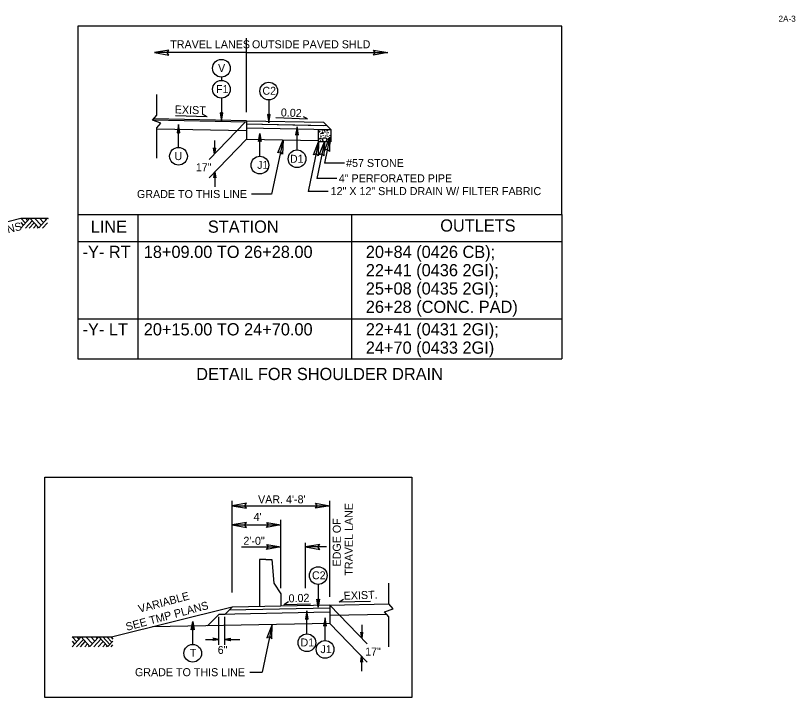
# Model space of a CAD drawing. Extents: x 1901582 to 1902252, y 193723 to 194156.
# Drawn here: x 1902064.9 to 1902128.8, y 193879.3 to 193935.2 of the extents above; entities that cross this region are included whole.
import ezdxf

# ---------------------------------------------------------------- set-up
doc = ezdxf.new("R2010")
doc.units = 0
for name, color, linetype in [('Old_Level_1', 7, 'Continuous'), ('Old_Level_11', 7, 'Continuous'), ('Old_Level_2', 7, 'Continuous'), ('Old_Level_20', 7, 'Continuous'), ('Old_Level_44', 7, 'Continuous'), ('Prop Dimension', 7, 'Continuous'), ('Typical Curb CELL', 7, 'Continuous'), ('Typical Median Barrier CELL', 7, 'Continuous'), ('Typical Pavement Slope Information CELL', 7, 'Continuous'), ('Typical Terminator CELL', 7, 'Continuous'), ('Typical Text Asphalt at Bridge Approach CELL', 7, 'Continuous')]:
    doc.layers.add(name, color=color, linetype=linetype)

msp = doc.modelspace()

# ---------------------------------------------------------------- linework, layer by layer
at = {"layer": 'Old_Level_1'}
for p, q in [((1902083.794, 193927.288), (1902083.794, 193933.361)), ((1902083.794, 193932.177), (1902076.259, 193932.177)), ((1902083.794, 193932.177), (1902095.364, 193932.177)), ((1902083.794, 193926.463), (1902076.121, 193926.617)), ((1902083.794, 193926.577), (1902076.174, 193926.73)), ((1902083.794, 193926.577), (1902090.11, 193926.451)), ((1902083.794, 193926.577), (1902083.794, 193925.077)), ((1902086.201, 193926.841), (1902088.787, 193926.739)), ((1902088.787, 193926.739), (1902088.457, 193926.912)), ((1902083.709, 193926.49), (1902080.725, 193923.408)), ((1902083.794, 193926.327), (1902090.365, 193926.196)), ((1902083.794, 193926.327), (1902090.104, 193926.201)), ((1902083.794, 193925.994), (1902090.705, 193925.856)), ((1902090.11, 193926.451), (1902090.705, 193925.856)), ((1902083.794, 193925.744), (1902076.442, 193925.891)), ((1902083.794, 193925.077), (1902080.725, 193921.908)), ((1902081.174, 193924.96), (1902081.174, 193923.872)), ((1902083.794, 193925.077), (1902089.705, 193924.959)), ((1902086.785, 193925.017), (1902085.851, 193920.553)), ((1902089.705, 193924.856), (1902088.855, 193920.794)), ((1902090.178, 193924.856), (1902089.548, 193921.842)), ((1902090.621, 193925.229), (1902090.175, 193923.098)), ((1902081.174, 193923.872), (1902081.09, 193924.349)), ((1902081.174, 193923.872), (1902081.102, 193924.34)), ((1902081.114, 193924.331), (1902081.174, 193923.872)), ((1902081.174, 193923.872), (1902081.126, 193924.323)), ((1902081.138, 193924.314), (1902081.174, 193923.872)), ((1902081.174, 193923.872), (1902081.15, 193924.305)), ((1902081.162, 193924.296), (1902081.174, 193923.872)), ((1902081.174, 193923.872), (1902081.259, 193924.349)), ((1902081.247, 193924.34), (1902081.174, 193923.872)), ((1902081.174, 193923.872), (1902081.234, 193924.331)), ((1902081.222, 193924.323), (1902081.174, 193923.872)), ((1902081.174, 193923.872), (1902081.21, 193924.314)), ((1902081.198, 193924.305), (1902081.174, 193923.872)), ((1902081.174, 193923.872), (1902081.186, 193924.296)), ((1902081.174, 193924.287), (1902081.174, 193923.872)), ((1902091.811, 193923.098), (1902090.175, 193923.098)), ((1902081.191, 193922.389), (1902081.107, 193921.911)), ((1902081.119, 193921.921), (1902081.191, 193922.389)), ((1902081.191, 193922.389), (1902081.131, 193921.929)), ((1902081.143, 193921.939), (1902081.191, 193922.389)), ((1902081.191, 193922.389), (1902081.155, 193921.947)), ((1902081.167, 193921.955), (1902081.191, 193922.389)), ((1902081.191, 193922.389), (1902081.179, 193921.964)), ((1902081.191, 193922.389), (1902081.276, 193921.911)), ((1902081.203, 193921.964), (1902081.191, 193922.389)), ((1902081.191, 193922.389), (1902081.215, 193921.955)), ((1902081.227, 193921.947), (1902081.191, 193922.389)), ((1902081.191, 193922.389), (1902081.239, 193921.939)), ((1902081.251, 193921.929), (1902081.191, 193922.389)), ((1902081.191, 193922.389), (1902081.264, 193921.921)), ((1902081.191, 193922.389), (1902081.191, 193921.163)), ((1902091.183, 193921.842), (1902089.548, 193921.842)), ((1902085.851, 193920.553), (1902084.216, 193920.553)), ((1902090.491, 193920.794), (1902088.855, 193920.794)), ((1902058.003, 193916.768), (1902065.307, 193918.594)), ((1902082.619, 193887.917), (1902082.619, 193895.416)), ((1902082.619, 193895.027), (1902090.619, 193895.027)), ((1902082.619, 193893.454), (1902086.619, 193893.454)), ((1902086.619, 193888.281), (1902086.619, 193893.86)), ((1902088.619, 193888.281), (1902088.619, 193891.983)), ((1902090.349, 193891.645), (1902088.619, 193891.645)), ((1902090.619, 193886.879), (1902095.451, 193886.975)), ((1902082.619, 193886.719), (1902072.852, 193884.277)), ((1902082.619, 193886.719), (1902082.024, 193886.123)), ((1902090.619, 193886.628), (1902082.364, 193886.463)), ((1902090.619, 193886.879), (1902082.619, 193886.719)), ((1902090.619, 193886.879), (1902090.619, 193885.378)), ((1902090.619, 193886.879), (1902093.688, 193883.709)), ((1902081.524, 193886.113), (1902080.589, 193885.178)), ((1902090.619, 193886.295), (1902081.524, 193886.113)), ((1902082.024, 193886.123), (1902081.524, 193886.113)), ((1902090.619, 193886.045), (1902095.271, 193886.138)), ((1902090.619, 193885.378), (1902076.097, 193885.088)), ((1902085.905, 193885.284), (1902085.088, 193881.375)), ((1902090.619, 193885.378), (1902093.688, 193882.209)), ((1902093.239, 193885.261), (1902093.239, 193884.173)), ((1902093.239, 193884.173), (1902093.154, 193884.65)), ((1902093.166, 193884.641), (1902093.239, 193884.173)), ((1902093.239, 193884.173), (1902093.179, 193884.632)), ((1902093.191, 193884.624), (1902093.239, 193884.173)), ((1902093.239, 193884.173), (1902093.203, 193884.615)), ((1902093.215, 193884.606), (1902093.239, 193884.173)), ((1902093.239, 193884.173), (1902093.227, 193884.597)), ((1902093.239, 193884.173), (1902093.323, 193884.65)), ((1902093.239, 193884.173), (1902093.311, 193884.641)), ((1902093.299, 193884.632), (1902093.239, 193884.173)), ((1902093.239, 193884.173), (1902093.287, 193884.624)), ((1902093.275, 193884.615), (1902093.239, 193884.173)), ((1902093.239, 193884.173), (1902093.263, 193884.606)), ((1902093.251, 193884.597), (1902093.239, 193884.173)), ((1902093.239, 193884.588), (1902093.239, 193884.173)), ((1902080.436, 193884.075), (1902081.524, 193884.075)), ((1902081.524, 193884.075), (1902081.047, 193884.159)), ((1902081.524, 193884.075), (1902081.047, 193883.99)), ((1902081.524, 193884.075), (1902081.056, 193884.147)), ((1902081.056, 193884.002), (1902081.524, 193884.075)), ((1902081.065, 193884.135), (1902081.524, 193884.075)), ((1902081.524, 193884.075), (1902081.065, 193884.015)), ((1902081.524, 193884.075), (1902081.073, 193884.123)), ((1902081.073, 193884.027), (1902081.524, 193884.075)), ((1902081.082, 193884.111), (1902081.524, 193884.075)), ((1902081.524, 193884.075), (1902081.082, 193884.039)), ((1902081.524, 193884.075), (1902081.091, 193884.099)), ((1902081.091, 193884.051), (1902081.524, 193884.075)), ((1902081.1, 193884.087), (1902081.524, 193884.075)), ((1902081.524, 193884.075), (1902081.1, 193884.063)), ((1902081.109, 193884.075), (1902081.524, 193884.075)), ((1902082.024, 193884.058), (1902082.502, 193884.142)), ((1902082.492, 193884.131), (1902082.024, 193884.058)), ((1902082.024, 193884.058), (1902082.484, 193884.119)), ((1902082.474, 193884.107), (1902082.024, 193884.058)), ((1902082.024, 193884.058), (1902082.466, 193884.094)), ((1902082.458, 193884.082), (1902082.024, 193884.058)), ((1902082.024, 193884.058), (1902082.449, 193884.07)), ((1902082.024, 193884.058), (1902082.502, 193883.974)), ((1902082.449, 193884.046), (1902082.024, 193884.058)), ((1902082.024, 193884.058), (1902082.458, 193884.034)), ((1902082.466, 193884.023), (1902082.024, 193884.058)), ((1902082.024, 193884.058), (1902082.474, 193884.011)), ((1902082.484, 193883.999), (1902082.024, 193884.058)), ((1902082.024, 193884.058), (1902082.492, 193883.985)), ((1902082.024, 193884.058), (1902083.25, 193884.058)), ((1902093.222, 193882.69), (1902093.138, 193882.212)), ((1902093.222, 193882.69), (1902093.149, 193882.222)), ((1902093.163, 193882.23), (1902093.222, 193882.69)), ((1902093.222, 193882.69), (1902093.175, 193882.24)), ((1902093.187, 193882.248), (1902093.222, 193882.69)), ((1902093.222, 193882.69), (1902093.198, 193882.256)), ((1902093.21, 193882.265), (1902093.222, 193882.69)), ((1902093.222, 193882.69), (1902093.306, 193882.212)), ((1902093.295, 193882.222), (1902093.222, 193882.69)), ((1902093.222, 193882.69), (1902093.283, 193882.23)), ((1902093.271, 193882.24), (1902093.222, 193882.69)), ((1902093.222, 193882.69), (1902093.258, 193882.248)), ((1902093.246, 193882.256), (1902093.222, 193882.69)), ((1902093.222, 193882.69), (1902093.234, 193882.265)), ((1902093.222, 193882.69), (1902093.222, 193881.464)), ((1902084.078, 193881.375), (1902085.088, 193881.375))]:
    msp.add_line(p, q, dxfattribs=at)
for points in [[(1902065.307, 193918.594), (1902067.543, 193918.594)], [(1902069.51, 193884.277), (1902072.852, 193884.277)]]:
    msp.add_lwpolyline(points, dxfattribs=at)
msp.add_lwpolyline([(1902097.341, 193879.316), (1902067.284, 193879.316), (1902067.284, 193897.368), (1902097.341, 193897.368)], close=True, dxfattribs=at)
at = {"layer": 'Old_Level_11'}
for p, q in [((1902081.741, 193930.16), (1902081.741, 193929.882)), ((1902081.741, 193928.432), (1902081.741, 193926.558)), ((1902085.618, 193928.288), (1902085.618, 193926.414)), ((1902078.225, 193924.396), (1902078.225, 193926.271)), ((1902087.932, 193924.188), (1902087.932, 193926.091)), ((1902084.89, 193923.669), (1902084.89, 193925.543)), ((1902069.979, 193918.885), (1902069.979, 193907.075)), ((1902074.892, 193918.885), (1902074.892, 193907.075)), ((1902092.407, 193918.885), (1902092.407, 193907.075)), ((1902109.632, 193918.885), (1902109.632, 193907.075)), ((1902065.307, 193918.594), (1902065.682, 193918.191)), ((1902065.307, 193917.789), (1902066.049, 193918.586)), ((1902065.681, 193917.789), (1902066.235, 193918.385)), ((1902065.682, 193918.594), (1902065.869, 193918.393)), ((1902066.049, 193918.586), (1902066.773, 193917.807)), ((1902066.44, 193918.594), (1902066.973, 193918.021)), ((1902066.773, 193917.807), (1902067.504, 193918.593)), ((1902066.838, 193918.594), (1902067.171, 193918.235)), ((1902067.24, 193918.594), (1902067.373, 193918.451)), ((1902067.504, 193918.593), (1902067.539, 193918.556)), ((1902065.307, 193918.232), (1902065.513, 193918.01)), ((1902065.99, 193917.789), (1902066.391, 193918.218)), ((1902066.337, 193917.789), (1902066.564, 193918.032)), ((1902066.648, 193917.789), (1902066.719, 193917.865)), ((1902067.083, 193917.789), (1902067.49, 193918.226)), ((1902069.979, 193916.681), (1902109.632, 193916.681)), ((1902069.979, 193910.332), (1902109.632, 193910.332)), ((1902069.979, 193907.075), (1902109.632, 193907.075)), ((1902089.668, 193888.58), (1902089.668, 193886.706)), ((1902088.743, 193884.526), (1902088.743, 193886.4)), ((1902090.234, 193883.976), (1902090.234, 193885.85)), ((1902079.387, 193883.66), (1902079.387, 193885.534)), ((1902069.51, 193884.277), (1902069.885, 193883.874)), ((1902069.51, 193883.472), (1902070.252, 193884.269)), ((1902069.51, 193883.915), (1902069.716, 193883.693)), ((1902069.884, 193883.472), (1902070.438, 193884.068)), ((1902069.885, 193884.277), (1902070.072, 193884.076)), ((1902070.193, 193883.472), (1902070.594, 193883.901)), ((1902070.252, 193884.269), (1902070.976, 193883.49)), ((1902070.643, 193884.277), (1902071.176, 193883.704)), ((1902070.976, 193883.49), (1902071.707, 193884.276)), ((1902071.041, 193884.277), (1902071.374, 193883.918)), ((1902071.286, 193883.472), (1902071.872, 193884.1)), ((1902071.443, 193884.277), (1902071.576, 193884.134)), ((1902071.656, 193883.472), (1902072.056, 193883.901)), ((1902071.707, 193884.276), (1902072.448, 193883.48)), ((1902072.029, 193884.277), (1902072.609, 193883.654)), ((1902072.362, 193884.277), (1902072.776, 193883.833)), ((1902072.448, 193883.48), (1902072.852, 193883.915)), ((1902072.682, 193884.277), (1902072.852, 193884.094)), ((1902070.54, 193883.472), (1902070.767, 193883.715)), ((1902070.851, 193883.472), (1902070.922, 193883.548)), ((1902072.022, 193883.472), (1902072.239, 193883.705)), ((1902072.317, 193883.472), (1902072.386, 193883.546)), ((1902072.718, 193883.472), (1902072.852, 193883.615))]:
    msp.add_line(p, q, dxfattribs=at)
for points in [[(1902109.632, 193934.341), (1902069.979, 193934.341), (1902069.979, 193918.885), (1902109.632, 193918.885)], [(1902081.625, 193927.229), (1902081.741, 193926.558), (1902081.86, 193927.233), (1902081.741, 193927.147)], [(1902085.502, 193927.085), (1902085.618, 193926.414), (1902085.737, 193927.089), (1902085.618, 193927.003)], [(1902078.341, 193925.599), (1902078.225, 193926.271), (1902078.106, 193925.595), (1902078.225, 193925.681)], [(1902088.048, 193925.419), (1902087.932, 193926.091), (1902087.813, 193925.416), (1902087.932, 193925.501)], [(1902084.775, 193924.871), (1902084.89, 193925.543), (1902085.01, 193924.868), (1902084.89, 193924.953)], [(1902089.784, 193887.377), (1902089.668, 193886.706), (1902089.549, 193887.381), (1902089.668, 193887.295)], [(1902088.858, 193885.729), (1902088.743, 193886.4), (1902088.623, 193885.725), (1902088.743, 193885.811)], [(1902090.349, 193885.179), (1902090.234, 193885.85), (1902090.114, 193885.175), (1902090.234, 193885.261)], [(1902079.272, 193884.863), (1902079.387, 193885.534), (1902079.507, 193884.859), (1902079.387, 193884.945)]]:
    msp.add_lwpolyline(points, close=True, dxfattribs=at)
for centre in [(1902081.741, 193930.885), (1902081.741, 193929.157), (1902085.618, 193929.013), (1902078.225, 193923.671), (1902087.932, 193923.463), (1902084.89, 193922.944), (1902089.668, 193889.305), (1902088.743, 193883.801), (1902090.233, 193883.251), (1902079.387, 193882.935)]:
    msp.add_circle(centre, 0.725, dxfattribs=at)
at = {"layer": 'Prop Dimension'}
for p, q in [((1902090.619, 193887.571), (1902090.619, 193895.416)), ((1902083.396, 193891.645), (1902086.619, 193891.645)), ((1902081.524, 193883.621), (1902081.524, 193885.914)), ((1902082.024, 193883.621), (1902082.024, 193885.914))]:
    msp.add_line(p, q, dxfattribs=at)
at = {"layer": 'Typical Curb CELL'}
for p, q in [((1902089.705, 193924.856), (1902089.705, 193925.856)), ((1902089.705, 193925.856), (1902090.705, 193925.856)), ((1902089.963, 193925.527), (1902090.052, 193925.645)), ((1902090.084, 193925.531), (1902089.963, 193925.527)), ((1902090.052, 193925.645), (1902090.084, 193925.531)), ((1902090.705, 193925.856), (1902090.705, 193924.856)), ((1902090.705, 193924.856), (1902089.705, 193924.856)), ((1902089.774, 193925.071), (1902089.838, 193925.185)), ((1902089.94, 193925.108), (1902089.774, 193925.071)), ((1902089.838, 193925.185), (1902089.94, 193925.108)), ((1902090.468, 193925.048), (1902090.532, 193925.162)), ((1902090.634, 193925.085), (1902090.468, 193925.048)), ((1902090.532, 193925.162), (1902090.634, 193925.085))]:
    msp.add_line(p, q, dxfattribs=at)
for centre, radius in [((1902089.709, 193925.321), 0.00802), ((1902089.721, 193925.629), 0.00802), ((1902089.74, 193925.726), 0.00802), ((1902089.775, 193925.485), 0.00802), ((1902089.796, 193925.69), 0.00802), ((1902089.841, 193925.316), 0.00802), ((1902089.872, 193925.529), 0.00802), ((1902089.907, 193925.813), 0.00802), ((1902089.919, 193925.294), 0.00802), ((1902090.002, 193925.726), 0.00802), ((1902090.05, 193925.827), 0.00802), ((1902090.08, 193925.359), 0.00802), ((1902090.197, 193925.761), 0.00802), ((1902090.223, 193925.659), 0.00802), ((1902090.285, 193925.332), 0.00802), ((1902090.37, 193925.57), 0.00802), ((1902090.401, 193925.416), 0.00802), ((1902090.402, 193925.741), 0.00802), ((1902090.42, 193925.791), 0.00802), ((1902090.456, 193925.3), 0.00802), ((1902090.496, 193925.596), 0.00802), ((1902090.535, 193925.293), 0.00802), ((1902090.634, 193925.36), 0.00802), ((1902090.676, 193925.758), 0.00802), ((1902089.85, 193924.927), 0.00802), ((1902090.205, 193925.022), 0.167), ((1902090.545, 193924.904), 0.00802)]:
    msp.add_circle(centre, radius, dxfattribs=at)
at = {"layer": 'Typical Median Barrier CELL'}
for p, q in [((1902085.37, 193890.631), (1902084.87, 193890.631)), ((1902084.87, 193890.631), (1902084.87, 193886.773)), ((1902085.37, 193890.631), (1902085.87, 193890.631)), ((1902085.87, 193890.631), (1902086.036, 193888.684)), ((1902086.036, 193888.684), (1902086.619, 193887.798)), ((1902086.619, 193887.798), (1902086.619, 193886.799))]:
    msp.add_line(p, q, dxfattribs=at)
at = {"layer": 'Typical Pavement Slope Information CELL'}
for p, q in [((1902080.565, 193926.889), (1902077.978, 193926.99)), ((1902080.565, 193926.889), (1902080.194, 193927.123)), ((1902086.861, 193886.936), (1902087.236, 193887.164)), ((1902086.861, 193886.936), (1902089.045, 193886.988)), ((1902091.374, 193887.15), (1902091.749, 193887.378)), ((1902091.374, 193887.15), (1902093.962, 193887.211))]:
    msp.add_line(p, q, dxfattribs=at)
at = {"layer": 'Typical Terminator CELL'}
for points in [[(1902077.431, 193932.379), (1902076.259, 193932.177), (1902077.437, 193931.969), (1902077.287, 193932.177)], [(1902094.192, 193932.379), (1902095.364, 193932.177), (1902094.185, 193931.969), (1902094.335, 193932.177)], [(1902086.36, 193923.942), (1902086.785, 193925.017), (1902086.749, 193923.854), (1902086.58, 193924.038)], [(1902089.279, 193923.78), (1902089.705, 193924.856), (1902089.669, 193923.692), (1902089.5, 193923.877)], [(1902089.753, 193923.78), (1902090.178, 193924.856), (1902090.142, 193923.692), (1902089.973, 193923.877)], [(1902090.195, 193924.153), (1902090.621, 193925.229), (1902090.585, 193924.065), (1902090.416, 193924.249)], [(1902083.791, 193895.228), (1902082.619, 193895.027), (1902083.798, 193894.818), (1902083.648, 193895.027)], [(1902089.448, 193895.228), (1902090.619, 193895.027), (1902089.441, 193894.818), (1902089.591, 193895.027)], [(1902083.791, 193893.656), (1902082.619, 193893.454), (1902083.798, 193893.246), (1902083.648, 193893.454)], [(1902085.448, 193893.656), (1902086.619, 193893.454), (1902085.441, 193893.246), (1902085.591, 193893.454)], [(1902085.448, 193891.847), (1902086.619, 193891.645), (1902085.441, 193891.437), (1902085.591, 193891.645)], [(1902089.791, 193891.847), (1902088.619, 193891.645), (1902089.798, 193891.437), (1902089.648, 193891.645)], [(1902085.864, 193884.128), (1902085.905, 193885.284), (1902085.472, 193884.204), (1902085.7, 193884.305)]]:
    msp.add_lwpolyline(points, close=True, dxfattribs=at)
at = {"layer": 'Typical Text Asphalt at Bridge Approach CELL'}
for points in [[(1902076.442, 193923.515), (1902076.442, 193925.99), (1902076.783, 193926.386), (1902076.087, 193926.629), (1902076.442, 193927.042), (1902076.445, 193928.744)], [(1902095.451, 193883.454), (1902095.451, 193885.929), (1902095.109, 193886.326), (1902095.805, 193886.568), (1902095.451, 193886.981), (1902095.447, 193888.683)]]:
    msp.add_lwpolyline(points, dxfattribs=at)

# ---------------------------------------------------------------- texts
at = {"layer": 'Old_Level_1'}
for s, p in [('TRAVEL LANES', (1902077.549, 193932.52)), ('OUTSIDE PAVED SHLD', (1902084.241, 193932.52)), ('#57 STONE', (1902091.953, 193922.79)), ('4" PERFORATED PIPE', (1902091.358, 193921.534)), ('GRADE TO THIS LINE', (1902074.823, 193920.246)), ('12" X 12" SHLD DRAIN W/ FILTER FABRIC', (1902090.689, 193920.486)), ("VAR. 4'-8'", (1902084.741, 193895.222)), ("4'", (1902084.375, 193893.788)), ('2\'-0"', (1902083.541, 193891.823)), ('GRADE TO THIS LINE', (1902074.658, 193881.055))]:
    msp.add_text(s, height=0.656, dxfattribs=at).set_placement(p)
for s, rotation, p in [('SEE X-SECTIONS', 14.03624, (1902058.302, 193915.861)), ('TRAVEL LANE', 90, (1902092.503, 193889.297)), ('EDGE OF', 90, (1902091.519, 193890.049)), ('VARIABLE', 15.042, (1902075.028, 193886.24)), ('SEE TMP PLANS', 15.042, (1902074.002, 193884.767))]:
    msp.add_text(s, height=0.656, rotation=rotation, dxfattribs=at).set_placement(p)
at = {"layer": 'Old_Level_11'}
for s, p in [('LINE', (1902071.036, 193917.402)), ('STATION', (1902080.63, 193917.402)), ('OUTLETS', (1902099.666, 193917.496)), ('-Y- RT ', (1902070.366, 193915.333)), ('18+09.00 TO 26+28.00', (1902075.38, 193915.333)), ('20+84 (0426 CB); ', (1902093.569, 193915.333)), ('22+41 (0436 2GI); ', (1902093.569, 193913.833)), ('25+08 (0435 2GI); ', (1902093.569, 193912.333)), ('26+28 (CONC. PAD)', (1902093.569, 193910.833)), ('-Y- LT ', (1902070.366, 193908.987)), ('20+15.00 TO 24+70.00', (1902075.38, 193908.987)), ('22+41 (0431 2GI); ', (1902093.569, 193908.987)), ('24+70 (0433 2GI)', (1902093.569, 193907.487)), ('DETAIL FOR SHOULDER DRAIN ', (1902079.675, 193905.327))]:
    msp.add_text(s, height=1, dxfattribs=at).set_placement(p)
at = {"layer": 'Old_Level_2'}
for s, rotation, p in [('EXIST', 358.02792, (1902077.913, 193927.187)), ('0.02', 357.74606, (1902086.6, 193926.942)), ('0.02', 1.97208, (1902087.253, 193887.104)), ('EXIST.', 1.97208, (1902091.765, 193887.318))]:
    msp.add_text(s, height=0.656, rotation=rotation, dxfattribs=at).set_placement(p)
at = {"layer": 'Old_Level_20'}
for s, height, p in [('V', 0.649, (1902081.467, 193930.579)), ('F1', 0.6491, (1902081.3, 193928.851)), ('C2', 0.6491, (1902085.102, 193928.713)), ('U', 0.649, (1902077.898, 193923.357)), ('D1', 0.6491, (1902087.358, 193923.139)), ('17"', 0.6491, (1902079.65, 193922.446)), ('J1', 0.6491, (1902084.672, 193922.64)), ('C2', 0.6491, (1902089.162, 193888.999)), ('D1', 0.6491, (1902088.221, 193883.497)), ('T', 0.649, (1902079.16, 193882.642)), ('6"', 0.6491, (1902081.44, 193882.884)), ('J1', 0.6491, (1902089.859, 193882.947)), ('17"', 0.6491, (1902093.52, 193882.747))]:
    msp.add_text(s, height=height, dxfattribs=at).set_placement(p)
at = {"layer": 'Old_Level_44'}
msp.add_text('2A-3', height=0.5, dxfattribs=at).set_placement((1902127.372, 193934.693))

doc.saveas('drawing.dxf')
